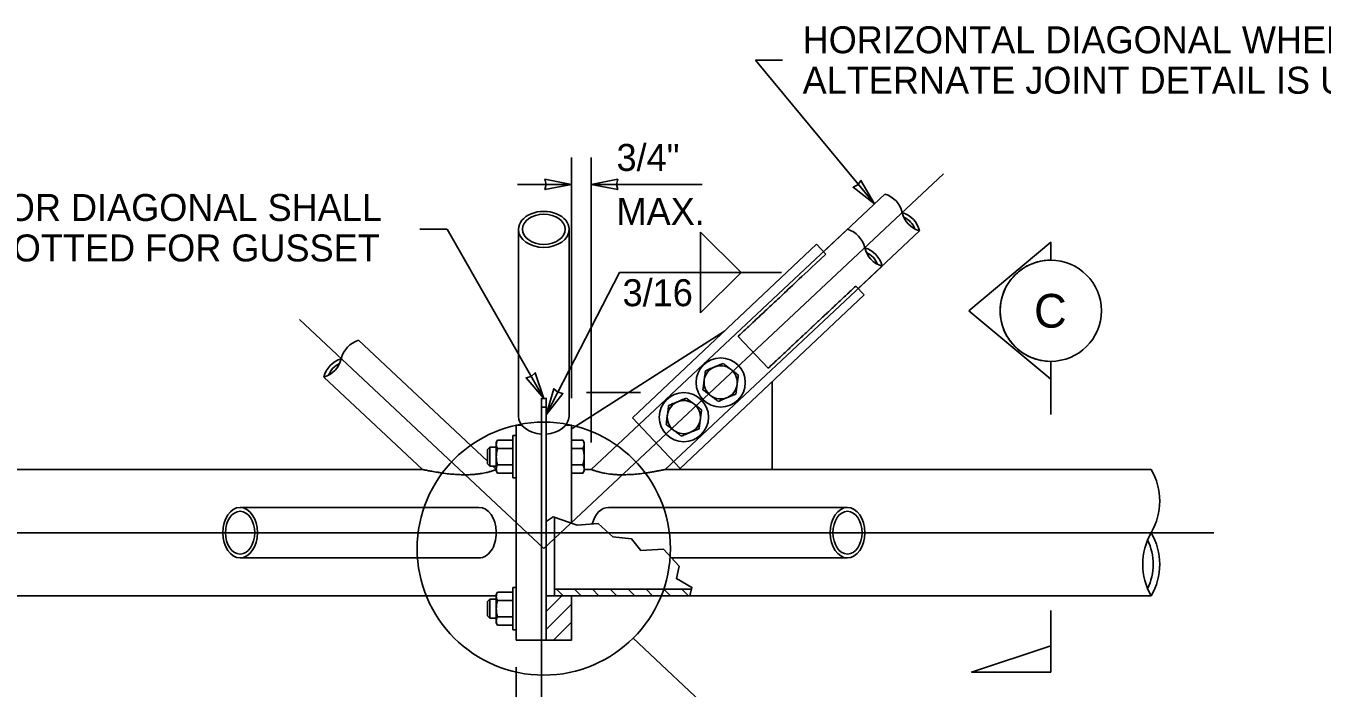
# Model space of a CAD drawing. Extents: x 99862 to 104211, y 98939 to 111076.
# Drawn here: x 101228 to 101996, y 106895 to 107288 of the extents above; entities that cross this region are included whole.
import ezdxf

# ---------------------------------------------------------------- set-up
doc = ezdxf.new("R2010")
doc.units = 0
for name, color, linetype in [('Level 1', 7, 'Continuous'), ('Level 11', 7, 'Continuous'), ('Level 12', 7, 'Continuous'), ('Level 13', 7, 'Continuous'), ('Level 14', 7, 'Continuous'), ('Level 15', 7, 'Continuous'), ('Level 20', 7, 'Continuous'), ('Level 4', 7, 'Continuous'), ('Level 5', 7, 'Continuous'), ('Level 7', 7, 'Continuous'), ('Level 9', 7, 'Continuous')]:
    doc.layers.add(name, color=color, linetype=linetype)

msp = doc.modelspace()

# ---------------------------------------------------------------- linework, layer by layer
at = {"layer": 'Level 1'}
for centre, radius, start, end in [((101732.38, 107174.18), 15, 13.18307, 73.18307), ((101761.58, 107181.03), 15, 193.18307, 253.18307), ((101742.64, 107163.25), 15, 13.18307, 73.18307), ((101742.64, 107163.25), 12.69, 21.10404, 65.26209), ((101710.16, 107153.32), 15, 13.18307, 73.18307), ((101720.43, 107142.38), 15, 13.18307, 73.18307), ((101739.37, 107160.16), 15, 193.18307, 253.18307), ((101720.43, 107142.38), 12.69, 21.10404, 65.26209), ((101429.11, 107087.44), 15, 106.81693, 166.81693), ((101418.85, 107076.5), 15, 106.81693, 166.81693), ((101399.9, 107094.28), 15, 286.81693, 346.81693), ((101418.85, 107076.5), 12.69, 114.73791, 158.89596), ((101862.07, 107006.43), 37.5, 330, 30), ((101927.02, 106968.93), 37.5, 150, 210), ((101862.07, 106968.93), 37.5, 330, 30), ((101862.07, 106968.93), 33.63, 334.5117, 25.4883)]:
    msp.add_arc(centre, radius, start, end, dxfattribs=at)
at = {"layer": 'Level 11'}
for p, q in [((101696.09, 107158.73), (101587.07, 107055.71)), ((101701.64, 107152.87), (101696.09, 107158.73)), ((101724.42, 107128.75), (101719.48, 107133.98)), ((101615.4, 107025.73), (101724.42, 107128.75)), ((101587.07, 107055.71), (101615.4, 107025.73))]:
    msp.add_line(p, q, dxfattribs=at)
at = {"layer": 'Level 12'}
for p, q in [((101533.14, 106923.93), (101533.14, 107067.39)), ((101535.95, 106923.93), (101535.95, 107067.39)), ((101535.95, 107062.04), (101533.14, 107062.04)), ((101540.95, 106950.18), (101540.95, 106996.82))]:
    msp.add_line(p, q, dxfattribs=at)
at = {"layer": 'Level 13'}
for p, q in [((101518.14, 107051.43), (101518.14, 106923.93)), ((101521.55, 107051.43), (101518.14, 107051.43)), ((101550.95, 106923.93), (101518.14, 106923.93))]:
    msp.add_line(p, q, dxfattribs=at)
at = {"layer": 'Level 14'}
for p, q in [((101547.53, 107051.43), (101550.95, 107051.43)), ((101550.95, 107051.43), (101550.95, 106993.36)), ((101550.95, 106950.18), (101550.95, 106923.93))]:
    msp.add_line(p, q, dxfattribs=at)
at = {"layer": 'Level 15'}
for p, q in [((101659.95, 107268.07), (101675.95, 107268.07)), ((101659.95, 107268.07), (101730.58, 107182.79)), ((101550.95, 107067.43), (101550.95, 107210.28)), ((101562.67, 107041.18), (101562.67, 107210.28)), ((101518.95, 107194.28), (101550.95, 107194.28)), ((101534.54, 106978.21), (101771.43, 107200.54)), ((101562.67, 107194.28), (101628.34, 107194.28)), ((101461.11, 107167.7), (101477.11, 107167.7)), ((101477.24, 107167.7), (101534.54, 107067.34)), ((101627.49, 107166.03), (101627.49, 107142.03)), ((101627.49, 107166.03), (101651.49, 107142.03)), ((101579.49, 107142.03), (101535.95, 107057.62)), ((101579.49, 107142.03), (101627.49, 107142.03)), ((101627.49, 107118.03), (101627.49, 107142.03)), ((101627.49, 107118.03), (101651.49, 107142.03)), ((101675.49, 107142.03), (101627.49, 107142.03)), ((101534.54, 106978.21), (101389.71, 107114.14)), ((101551.42, 107049.55), (101641.58, 107107.22)), ((101559.84, 107070.93), (101591.84, 107070.93)), ((101669.91, 107077.24), (101669.91, 107025.14)), ((101137.52, 106987.68), (101931.57, 106987.68)), ((101587.6, 106925.15), (101734.16, 106787.29)), ((101533.14, 106923.93), (101533.14, 106826.65)), ((101518.14, 106907.93), (101518.14, 106826.65))]:
    msp.add_line(p, q, dxfattribs=at)
for points in [[(101550.95, 107194.28), (101535.22, 107191.2), (101535.95, 107194.28), (101535.22, 107197.37)], [(101562.67, 107194.28), (101578.39, 107191.2), (101577.66, 107194.28), (101578.39, 107197.37)], [(101730.58, 107182.79), (101717.89, 107192.57), (101720.69, 107194.06), (101722.53, 107196.64)], [(101534.54, 107067.34), (101524.07, 107079.47), (101527.11, 107080.37), (101529.43, 107082.53)], [(101535.95, 107057.62), (101540.42, 107073.01), (101542.82, 107070.95), (101545.9, 107070.18)]]:
    msp.add_lwpolyline(points, close=True, dxfattribs=at)
msp.add_circle((101534.54, 106978.21), 75.04, dxfattribs=at)
at = {"layer": 'Level 4'}
for p, q in [((101519.54, 107167.68), (101519.54, 107056.73)), ((101549.54, 107056.73), (101549.54, 107167.68)), ((101462.58, 107025.18), (101174.54, 107025.18)), ((101562.67, 107025.18), (101558.45, 107025.18)), ((101894.54, 107025.18), (101606.5, 107025.18)), ((101496.15, 107002.68), (101354.54, 107002.68)), ((101714.54, 107002.68), (101572.93, 107002.68)), ((101354.54, 106972.68), (101496.15, 106972.68)), ((101610.29, 106972.68), (101714.54, 106972.68)), ((101174.54, 106950.18), (101506.42, 106950.18)), ((101535.95, 106950.18), (101894.54, 106950.18)), ((101535.95, 106940.86), (101545.27, 106950.18)), ((101540.95, 106954.08), (101622.07, 106954.08)), ((101546.04, 106950.18), (101542.14, 106954.08)), ((101556.65, 106950.18), (101552.75, 106954.08)), ((101567.25, 106950.18), (101563.35, 106954.08)), ((101577.86, 106950.18), (101573.96, 106954.08)), ((101588.47, 106950.18), (101584.57, 106954.08)), ((101599.07, 106950.18), (101595.17, 106954.08)), ((101609.68, 106950.18), (101605.78, 106954.08)), ((101620.29, 106950.18), (101616.39, 106954.08)), ((101535.95, 106930.25), (101550.95, 106945.25)), ((101540.23, 106923.93), (101550.95, 106934.64)), ((101550.84, 106923.93), (101550.95, 106924.04))]:
    msp.add_line(p, q, dxfattribs=at)
msp.add_lwpolyline([(101535.95, 106994.36), (101540.14, 106997.1), (101554.28, 106992.21), (101566.85, 106993.08), (101575.4, 106985.23), (101586.58, 106984.01), (101592.16, 106977.02), (101605.43, 106977.89), (101614.86, 106967.77), (101613.11, 106960.44), (101622.36, 106955.2), (101621.07, 106950.18)], dxfattribs=at)
for centre, major_axis, ratio, start_param, end_param in [((101534.54, 107167.68), (15, 0), 0.707107, 0, 3.141593), ((101534.54, 107167.53), (15, 0), 0.707107, 3.141593, 6.283185), ((101534.54, 107056.73), (-15, 0), 0.707107, 0, 1.476908), ((101534.54, 107056.73), (-15, 0), 0.707107, 1.664684, 3.141593), ((101496.15, 106987.68), (0, -15), 0.684332, 1.602826, 3.141593), ((101572.93, 106987.68), (0, -15), 0.684332, 3.141593, 4.361403), ((101496.15, 106987.68), (0, -15), 0.684332, 0, 1.570887), ((101496.15, 106987.68), (0, -15), 0.684332, 1.570887, 1.602826)]:
    msp.add_ellipse(centre, major_axis=major_axis, ratio=ratio, start_param=start_param, end_param=end_param, dxfattribs=at)
for centre, major_axis in [((101354.54, 106987.68), (0, -15)), ((101714.54, 106987.68), (0, -15)), ((101354.54, 106987.68), (0, -12.66)), ((101714.54, 106987.68), (0, -12.66))]:
    msp.add_ellipse(centre, major_axis=major_axis, ratio=0.684332, dxfattribs=at)
for points in [[(101506.42, 107025.18), (101506.42, 107025.18), (101506.39, 107025.17), (101506.33, 107025.15), (101506.17, 107025.08), (101505.77, 107024.93), (101505.14, 107024.71), (101504.52, 107024.49), (101503.66, 107024.21), (101502.64, 107023.92), (101501.58, 107023.62), (101500.33, 107023.31), (101498.97, 107023.05), (101497.16, 107022.69), (101495.13, 107022.41), (101493.07, 107022.25), (101490.16, 107022.02), (101487.11, 107022), (101484.17, 107022.13), (101480.17, 107022.32), (101476.19, 107022.79), (101472.58, 107023.34), (101470.73, 107023.62), (101468.94, 107023.93), (101467.36, 107024.22), (101466.16, 107024.45), (101465.06, 107024.67), (101464.2, 107024.84), (101463.64, 107024.96), (101463.17, 107025.05), (101462.89, 107025.11), (101462.69, 107025.15), (101462.58, 107025.18), (101462.58, 107025.18)], [(101606.5, 107025.18), (101606.5, 107025.18), (101606.39, 107025.15), (101606.19, 107025.11), (101605.95, 107025.06), (101605.58, 107024.98), (101605.12, 107024.89), (101604.33, 107024.73), (101603.28, 107024.52), (101602.14, 107024.3), (101600.16, 107023.93), (101597.83, 107023.52), (101595.42, 107023.17), (101591.74, 107022.64), (101587.73, 107022.22), (101583.71, 107022.09), (101581.01, 107022), (101578.23, 107022.05), (101575.58, 107022.29), (101573.61, 107022.46), (101571.66, 107022.74), (101569.92, 107023.08), (101568.47, 107023.37), (101567.14, 107023.71), (101566.06, 107024.03), (101564.96, 107024.35), (101564.09, 107024.65), (101563.51, 107024.86), (101562.99, 107025.05), (101562.7, 107025.17), (101562.67, 107025.18), (101562.67, 107025.18), (101562.67, 107025.18), (101562.67, 107025.18)]]:
    msp.add_open_spline(points, degree=3, dxfattribs=at)
at = {"layer": 'Level 5'}
for p, q in [((101736.72, 107188.54), (101700.26, 107154.33)), ((101714.5, 107167.68), (101562.67, 107025.18)), ((101720.86, 107132.52), (101757.32, 107166.74)), ((101606.5, 107025.18), (101735.03, 107145.8)), ((101501.26, 107030.02), (101424.77, 107101.8)), ((101667.53, 107085.22), (101649.68, 107104.11)), ((101404.24, 107079.92), (101462.58, 107025.18)), ((101506.42, 107025.18), (101504.33, 107027.13)), ((101506.42, 107025.18), (101506.42, 107025.18)), ((101562.67, 107025.18), (101562.67, 107025.18))]:
    msp.add_line(p, q, dxfattribs=at)
for points, degree in [([(101649.68, 107104.11), (101650.79, 107105.15), (101651.91, 107106.19), (101653.02, 107107.24), (101660.31, 107114.08), (101667.6, 107120.92), (101674.89, 107127.77), (101683.81, 107136.13), (101692.72, 107144.5), (101701.64, 107152.87)], 3), ([(101719.48, 107133.98), (101702.16, 107117.73), (101684.85, 107101.48), (101667.53, 107085.22)], 2)]:
    msp.add_open_spline(points, degree=degree, dxfattribs=at)
at = {"layer": 'Level 7'}
msp.add_ellipse((101534.54, 107167.68), major_axis=(12.66, 0), ratio=0.707107, dxfattribs=at)
msp.add_ellipse((101534.54, 107077.95), major_axis=(15, 0), ratio=0.707107, start_param=4.618501, end_param=4.806277, dxfattribs=at)
at = {"layer": 'Level 9'}
for p, q in [((101835.01, 107159.92), (101786.55, 107119.32)), ((101835.01, 107149.32), (101835.01, 107159.92)), ((101786.55, 107119.32), (101835.01, 107078.72)), ((101835.01, 107078.72), (101835.01, 107089.32)), ((101835.01, 107087.76), (101835.01, 107057.76)), ((101645.19, 107084.77), (101645.52, 107084.52)), ((101649.16, 107075.82), (101649.09, 107075.29)), ((101623.39, 107064.16), (101623.72, 107063.91)), ((101633.49, 107068.94), (101633.28, 107069.09)), ((101643.37, 107067.83), (101642.92, 107067.65)), ((101627.36, 107055.21), (101627.29, 107054.68)), ((101611.68, 107048.33), (101611.48, 107048.49)), ((101621.56, 107047.23), (101621.11, 107047.04)), ((101507.17, 107042.5), (101506.42, 107041.19)), ((101506.42, 107041.19), (101506.42, 107040.18)), ((101506.42, 107040.18), (101506.42, 107039.95)), ((101506.42, 107039.95), (101506.42, 107032.97)), ((101507.17, 107042.5), (101516.26, 107042.5)), ((101516.26, 107045.26), (101518.14, 107045.26)), ((101516.26, 107020.26), (101516.26, 107045.26)), ((101516.26, 107042.5), (101516.26, 107037.63)), ((101557.69, 107042.49), (101550.95, 107042.49)), ((101558.45, 107041.19), (101557.69, 107042.49)), ((101558.45, 107040.11), (101558.45, 107041.19)), ((101558.45, 107040), (101558.45, 107040.11)), ((101558.45, 107032.96), (101558.45, 107040)), ((101502.59, 107038.38), (101501.26, 107037.06)), ((101501.26, 107028.46), (101501.26, 107037.06)), ((101502.59, 107027.13), (101502.59, 107038.38)), ((101506.42, 107038.38), (101502.59, 107038.38)), ((101506.42, 107032.97), (101506.42, 107032.55)), ((101506.42, 107032.55), (101506.42, 107025.51)), ((101507.17, 107037.63), (101516.26, 107037.63)), ((101516.26, 107037.63), (101516.26, 107027.88)), ((101557.69, 107037.62), (101550.95, 107037.62)), ((101558.45, 107032.54), (101558.45, 107032.96)), ((101558.45, 107025.56), (101558.45, 107032.54)), ((101501.26, 107028.46), (101502.59, 107027.13)), ((101502.59, 107027.13), (101506.42, 107027.13)), ((101506.42, 107025.51), (101506.42, 107025.39)), ((101506.42, 107025.39), (101506.42, 107024.32)), ((101506.42, 107024.32), (101507.17, 107023.01)), ((101507.17, 107027.88), (101516.26, 107027.88)), ((101516.26, 107027.88), (101516.26, 107023.01)), ((101557.7, 107027.88), (101550.95, 107027.88)), ((101557.7, 107023.01), (101558.45, 107024.31)), ((101558.45, 107025.33), (101558.45, 107025.56)), ((101558.45, 107024.31), (101558.45, 107025.33)), ((101507.17, 107023.01), (101516.26, 107023.01)), ((101516.26, 107020.26), (101518.14, 107020.26)), ((101557.7, 107023.01), (101550.95, 107023.01)), ((101516.26, 106930.1), (101516.26, 106955.1)), ((101516.26, 106955.1), (101518.14, 106955.1)), ((101502.59, 106948.23), (101501.26, 106946.9)), ((101502.59, 106936.98), (101502.59, 106948.23)), ((101506.42, 106948.23), (101502.59, 106948.23)), ((101507.17, 106952.34), (101506.42, 106951.04)), ((101506.42, 106951.04), (101506.42, 106950.02)), ((101506.42, 106950.02), (101506.42, 106949.79)), ((101506.42, 106949.79), (101506.42, 106942.81)), ((101507.17, 106952.34), (101516.26, 106952.34)), ((101507.17, 106947.47), (101516.26, 106947.47)), ((101516.26, 106952.34), (101516.26, 106947.47)), ((101516.26, 106947.47), (101516.26, 106937.73)), ((101501.26, 106938.3), (101501.26, 106946.9)), ((101506.42, 106942.81), (101506.42, 106942.39)), ((101506.42, 106942.39), (101506.42, 106935.35)), ((101835.01, 106941.49), (101835.01, 106904.96)), ((101501.26, 106938.3), (101502.59, 106936.98)), ((101502.59, 106936.98), (101506.42, 106936.98)), ((101506.42, 106935.35), (101506.42, 106935.24)), ((101506.42, 106935.24), (101506.42, 106934.16)), ((101506.42, 106934.16), (101507.17, 106932.86)), ((101507.17, 106937.73), (101516.26, 106937.73)), ((101507.17, 106932.86), (101516.26, 106932.86)), ((101516.26, 106937.73), (101516.26, 106932.86)), ((101516.26, 106930.1), (101518.14, 106930.1))]:
    msp.add_line(p, q, dxfattribs=at)
msp.add_lwpolyline([(101835.01, 106920.49), (101788.13, 106904.96), (101835.01, 106904.96)], close=True, dxfattribs=at)
for centre, radius in [((101835.01, 107119.32), 30), ((101639.39, 107076.78), 14.58), ((101617.59, 107056.17), 14.58)]:
    msp.add_circle(centre, radius, dxfattribs=at)
for centre, radius, start, end in [((101835.01, 107119.32), 30, 89.99779, 270.00221), ((101639.37, 107076.83), 9.84, 112.54016, 231.78477), ((101639.37, 107076.83), 9.84, 53.73705, 112.54016), ((101639.37, 107076.83), 9.84, 354.10099, 51.34326), ((101639.37, 107076.83), 9.84, 293.95692, 350.97932), ((101617.57, 107056.22), 9.84, 112.54016, 231.78477), ((101617.57, 107056.22), 9.84, 53.73705, 112.54016), ((101617.57, 107056.22), 9.84, 354.10099, 51.34326), ((101639.37, 107076.83), 9.84, 233.29815, 291.12339), ((101617.57, 107056.22), 9.84, 293.95692, 350.97932), ((101617.57, 107056.22), 9.84, 233.29815, 291.12339)]:
    msp.add_arc(centre, radius, start, end, dxfattribs=at)
for points, degree in [([(101635.6, 107085.92), (101634.71, 107085.55), (101633.81, 107085.18), (101632.06, 107084.45), (101631.2, 107084.09), (101630.35, 107083.74)], 3), ([(101640.84, 107088.1), (101639.99, 107087.74), (101639.12, 107087.38), (101637.37, 107086.65), (101636.48, 107086.29), (101635.6, 107085.92)], 3), ([(101640.84, 107088.1), (101642.27, 107087.01), (101643.71, 107085.9), (101645.19, 107084.77)], 2), ([(101628.87, 107072.47), (101629.11, 107074.31), (101629.36, 107076.18), (101629.73, 107079.05), (101629.86, 107080.01), (101630.11, 107081.89), (101630.23, 107082.82), (101630.35, 107083.74)], 3), ([(101645.52, 107084.52), (101646.26, 107083.95), (101646.99, 107083.39), (101648.44, 107082.28), (101649.16, 107081.73), (101649.87, 107081.19)], 3), ([(101649.87, 107081.19), (101649.64, 107079.43), (101649.4, 107077.64), (101649.16, 107075.82)], 2), ([(101633.28, 107069.09), (101632.53, 107069.67), (101631.79, 107070.24), (101630.32, 107071.37), (101629.59, 107071.92), (101628.87, 107072.47)], 3), ([(101649.09, 107075.29), (101648.85, 107073.46), (101648.62, 107071.67), (101648.39, 107069.92)], 2), ([(101607.07, 107051.87), (101607.31, 107053.71), (101607.55, 107055.58), (101607.93, 107058.45), (101608.05, 107059.41), (101608.3, 107061.29), (101608.42, 107062.22), (101608.54, 107063.14)], 3), ([(101613.79, 107065.32), (101612.9, 107064.95), (101612, 107064.57), (101610.25, 107063.85), (101609.39, 107063.49), (101608.54, 107063.14)], 3), ([(101619.04, 107067.49), (101618.19, 107067.14), (101617.31, 107066.78), (101615.56, 107066.05), (101614.68, 107065.68), (101613.79, 107065.32)], 3), ([(101619.04, 107067.49), (101620.46, 107066.4), (101621.91, 107065.3), (101623.39, 107064.16)], 2), ([(101623.72, 107063.91), (101624.45, 107063.34), (101625.19, 107062.78), (101626.64, 107061.67), (101627.35, 107061.12), (101628.06, 107060.58)], 3), ([(101637.89, 107065.56), (101636.45, 107066.67), (101634.99, 107067.79), (101633.49, 107068.94)], 2), ([(101642.92, 107067.65), (101642.07, 107067.29), (101641.21, 107066.94), (101639.53, 107066.24), (101638.71, 107065.9), (101637.89, 107065.56)], 3), ([(101648.39, 107069.92), (101647.57, 107069.58), (101646.74, 107069.23), (101645.06, 107068.53), (101644.22, 107068.19), (101643.37, 107067.83)], 3), ([(101627.29, 107054.68), (101627.05, 107052.85), (101626.82, 107051.07), (101626.59, 107049.31)], 2), ([(101628.06, 107060.58), (101627.83, 107058.82), (101627.6, 107057.04), (101627.36, 107055.21)], 2), ([(101611.48, 107048.49), (101610.73, 107049.06), (101609.98, 107049.64), (101608.51, 107050.76), (101607.79, 107051.32), (101607.07, 107051.87)], 3), ([(101616.09, 107044.96), (101614.65, 107046.06), (101613.18, 107047.18), (101611.68, 107048.33)], 2), ([(101621.11, 107047.04), (101620.26, 107046.69), (101619.4, 107046.33), (101617.73, 107045.64), (101616.9, 107045.29), (101616.09, 107044.96)], 3), ([(101626.59, 107049.31), (101625.77, 107048.97), (101624.93, 107048.63), (101623.25, 107047.93), (101622.41, 107047.58), (101621.56, 107047.23)], 3), ([(101507.17, 107042.5), (101506.73, 107041.74), (101506.44, 107040.97), (101506.42, 107040.18)], 2), ([(101506.42, 107039.95), (101506.44, 107039.16), (101506.73, 107038.38), (101507.17, 107037.63)], 2), ([(101507.09, 107042.35), (101507.11, 107042.4), (101507.14, 107042.45), (101507.17, 107042.5)], 2), ([(101558.45, 107040.11), (101558.44, 107040.92), (101558.14, 107041.72), (101557.69, 107042.49)], 2), ([(101557.69, 107037.62), (101558.14, 107038.4), (101558.44, 107039.19), (101558.45, 107040)], 2), ([(101507.17, 107037.63), (101506.73, 107036.11), (101506.44, 107034.54), (101506.42, 107032.97)], 2), ([(101506.42, 107032.55), (101506.44, 107030.97), (101506.73, 107029.39), (101507.17, 107027.88)], 2), ([(101558.45, 107032.96), (101558.42, 107034.54), (101558.13, 107036.11), (101557.69, 107037.62)], 2), ([(101557.7, 107027.88), (101558.13, 107029.4), (101558.42, 107030.97), (101558.45, 107032.54)], 2), ([(101507.17, 107027.88), (101506.72, 107027.11), (101506.43, 107026.32), (101506.42, 107025.51)], 2), ([(101506.42, 107025.39), (101506.43, 107024.59), (101506.72, 107023.79), (101507.17, 107023.01)], 2), ([(101558.45, 107025.56), (101558.42, 107026.35), (101558.13, 107027.12), (101557.7, 107027.88)], 2), ([(101557.7, 107023.01), (101558.13, 107023.77), (101558.42, 107024.54), (101558.45, 107025.33)], 2), ([(101557.78, 107023.15), (101557.75, 107023.11), (101557.72, 107023.06), (101557.7, 107023.01)], 2), ([(101507.17, 106952.34), (101506.73, 106951.58), (101506.44, 106950.81), (101506.42, 106950.02)], 2), ([(101506.42, 106949.79), (101506.44, 106949), (101506.73, 106948.23), (101507.17, 106947.47)], 2), ([(101507.17, 106947.47), (101506.73, 106945.95), (101506.44, 106944.38), (101506.42, 106942.81)], 2), ([(101507.09, 106952.2), (101507.11, 106952.24), (101507.14, 106952.29), (101507.17, 106952.34)], 2), ([(101506.42, 106942.39), (101506.44, 106940.81), (101506.73, 106939.24), (101507.17, 106937.73)], 2), ([(101507.17, 106937.73), (101506.72, 106936.95), (101506.43, 106936.16), (101506.42, 106935.35)], 2), ([(101506.42, 106935.24), (101506.43, 106934.43), (101506.72, 106933.64), (101507.17, 106932.86)], 2)]:
    msp.add_open_spline(points, degree=degree, dxfattribs=at)

# ---------------------------------------------------------------- texts
at = {"layer": 'Level 15'}
for s, p in [('3/4"', (101577.66, 107202.28)), ('INTERIOR DIAGONAL SHALL', (101146.17, 107172.58)), ('MAX.', (101577.66, 107170.28)), ('BE SLOTTED FOR GUSSET', (101159.17, 107148.58))]:
    msp.add_text(s, height=16, dxfattribs=at).set_placement(p)
msp.add_text('3/16', height=16, rotation=360, dxfattribs=at).set_placement((101581.24, 107122.03))
at = {"layer": 'Level 20'}
for s, height, p in [('HORIZONTAL DIAGONAL WHEN', 16, (101687.95, 107272.07)), ('ALTERNATE JOINT DETAIL IS USED', 16, (101687.95, 107248.07)), ('C', 20, (101825.12, 107109.3))]:
    msp.add_text(s, height=height, dxfattribs=at).set_placement(p)

doc.saveas('drawing.dxf')
